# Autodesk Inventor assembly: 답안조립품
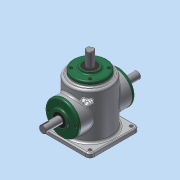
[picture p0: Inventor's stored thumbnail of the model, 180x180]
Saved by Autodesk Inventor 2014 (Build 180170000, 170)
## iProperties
Created: 2015-10
Part Number: 답안조립품
Document SubType Name: Assembly
Designer: net
Author: net
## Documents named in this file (14)
- C:\Users\net\Desktop\451007V1024\답안조립품.iam
- C:\Users\net\Desktop\451007V1024\답안조립품.ipt
- C:\Users\net\Desktop\451007V1024\메인 축.ipt
- 메인 축.ipt
- C:\Users\net\Desktop\451007V1024\베어링 6203.ipt
- C:\Users\net\Desktop\451007V1024\키 5x5.ipt
- C:\Users\net\Desktop\451007V1024\커버.ipt
- C:\Users\net\Desktop\451007V1024\서브 축.ipt
- 서브 축.ipt
- C:\Users\net\Desktop\451007V1024\키 4x4.ipt
- C:\Users\net\Desktop\451007V1024\서브 베벨기어.ipt
- C:\Users\net\Desktop\451007V1024\메인 베벨기어.ipt
- C:\Users\net\Desktop\451007V1024\오일실.ipt
- C:\Users\net\Desktop\451007V1024\M4.ipt
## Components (12 placed, 1 different names)
1. M4:2
2. M4:4
3. M4:5
4. M4:6
5. M4:3
6. M4:7
7. M4:8
8. M4:9
9. M4:10
10. M4:11
11. M4:12
12. M4:13
